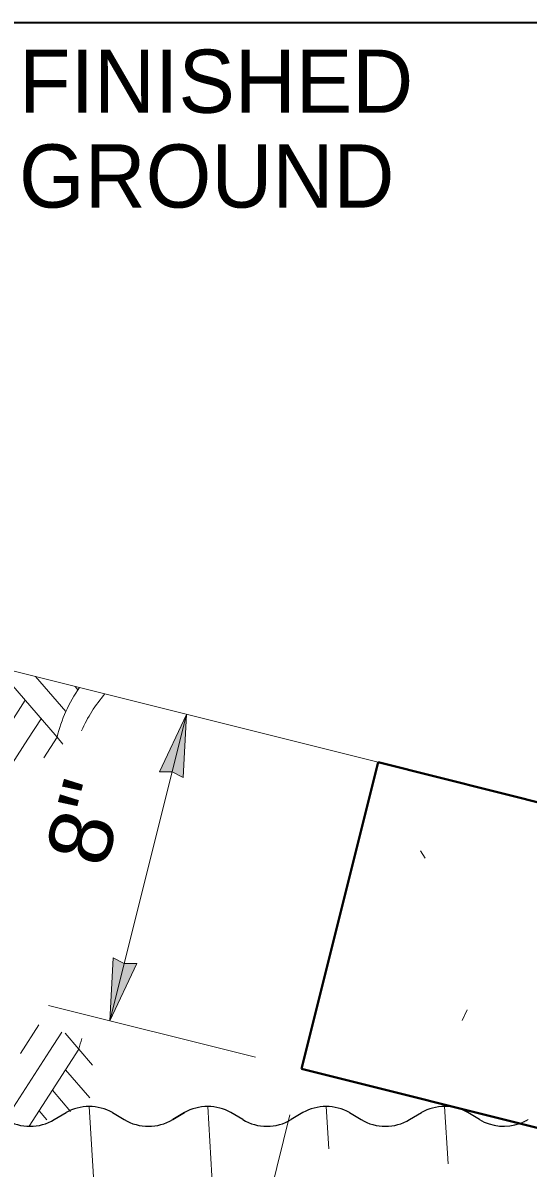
# Model space of a CAD drawing. Extents: x 99860 to 103153, y 99998 to 102077.
# Drawn here: x 100809.3 to 100937.3, y 101785.5 to 102075.5 of the extents above; entities that cross this region are included whole.
import ezdxf
from ezdxf.enums import TextEntityAlignment as Align

# ---------------------------------------------------------------- set-up
doc = ezdxf.new("R2010")
doc.units = 0
doc.header["$LTSCALE"] = 6.4
doc.linetypes.add('MEDIUM_DASHED', pattern=[4.5, 3, -1.5])
for name, color, linetype, lineweight in [('1', 7, 'Continuous', 13), ('13', 7, 'Continuous', 40), ('15', 7, 'Continuous', 13), ('17', 7, 'Continuous', 13), ('20', 7, 'Continuous', 13)]:
    doc.layers.add(name, color=color, linetype=linetype, lineweight=lineweight)

msp = doc.modelspace()

# ---------------------------------------------------------------- hatches: boundary and pattern name
at = {"layer": '15'}
for points in [[(100850.757, 101900.416), (100843.952, 101885.908), (100847.12, 101885.866), (100849.935, 101884.412)], [(100831.354, 101822.804), (100838.16, 101837.312), (100834.992, 101837.353), (100832.176, 101838.808)]]:
    msp.add_hatch(color=256, dxfattribs=at).paths.add_polyline_path(points)

# ---------------------------------------------------------------- linework, layer by layer
at = {"layer": '1'}
for p, q in [((100802.509, 101912.504), (100817.976, 101894.63)), ((100812.53, 101910), (100820.202, 101901.134)), ((100822.552, 101907.496), (100823.266, 101906.67)), ((100803.163, 101893.594), (100809.879, 101903.987)), ((100810.569, 101894.112), (100813.927, 101899.308)), ((100814.619, 101889.435), (100817.976, 101894.63)), ((100817.976, 101894.63), (100819.465, 101892.909)), ((100801.434, 101879.975), (100810.569, 101894.112)), ((100808.687, 101814.591), (100813.329, 101821.775)), ((100816.094, 101815.109), (100819.209, 101819.93)), ((100819.987, 101819.686), (100823.5, 101815.626)), ((100806.958, 101800.971), (100816.094, 101815.109)), ((100810.938, 101796.187), (100823.5, 101815.626)), ((100823.5, 101815.626), (100826.95, 101811.64)), ((100820.142, 101810.43), (100826.294, 101803.321)), ((100816.784, 101805.233), (100821.406, 101799.892)), ((100813.426, 101800.037), (100815.404, 101797.751)), ((100841.12, 101551.125), (100826.12, 101801.125)), ((100871.12, 101551.125), (100856.12, 101801.125)), ((100886.76, 101790.459), (100886.12, 101801.125)), ((100916.992, 101786.6), (100916.12, 101801.125))]:
    msp.add_line(p, q, dxfattribs=at)
at = {"layer": '1', "lineweight": 25}
for p, q in [((100817.259, 101797.811), (100820.246, 101799.589)), ((100831.995, 101799.589), (100834.982, 101797.811)), ((100847.259, 101797.811), (100850.246, 101799.589)), ((100847.259, 101797.811), (100850.246, 101799.589)), ((100850.246, 101799.589), (100847.259, 101797.811)), ((100864.982, 101797.811), (100861.995, 101799.589)), ((100880.246, 101799.589), (100877.259, 101797.811)), ((100891.995, 101799.589), (100894.982, 101797.811)), ((100907.259, 101797.811), (100910.246, 101799.589))]:
    msp.add_line(p, q, dxfattribs=at)
at = {"layer": '1', "lineweight": 35}
msp.add_lwpolyline([(99862, 99999.5), (103151, 99999.5), (103151, 102075.5), (99862, 102075.5)], close=True, dxfattribs=at)
at = {"layer": '1', "lineweight": 25}
for points in [[(100831.995, 101799.589), (100834.982, 101797.811), (100834.983, 101797.813)], [(100847.258, 101797.813), (100847.259, 101797.811), (100850.246, 101799.589)], [(100924.983, 101797.813), (100924.982, 101797.811), (100921.995, 101799.589)]]:
    msp.add_lwpolyline(points, dxfattribs=at)
at = {"layer": '1'}
for centre, start, end in [((100854.493, 101885.766), 145.1795, 166.3566), ((100858.541, 101881.087), 139.25013, 156.14215), ((100860.017, 101806.763), 162.05111, 166.3566)]:
    msp.add_arc(centre, 37.577, start, end, dxfattribs=at)
at = {"layer": '1', "lineweight": 25}
for centre, start, end in [((100826.12, 101789.125), 90, 119.31291), ((100826.12, 101789.125), 60.68709, 90), ((100826.12, 101789.125), 60.68709, 90), ((100856.12, 101789.125), 90, 119.31291), ((100856.12, 101789.125), 90, 119.31291), ((100856.12, 101789.125), 90, 119.31291), ((100856.12, 101789.125), 90, 119.31291), ((100856.12, 101789.125), 60.68709, 90), ((100886.12, 101789.125), 90, 119.31291), ((100886.12, 101789.125), 60.68709, 90), ((100916.12, 101789.125), 90, 119.31291), ((100916.12, 101789.125), 60.68709, 90), ((100811.12, 101808.125), 239.24007, 300.75993), ((100841.12, 101808.125), 239.24007, 300.75993), ((100841.12, 101808.125), 239.24007, 300.75993), ((100841.12, 101808.125), 239.24007, 300.75993), ((100841.12, 101808.125), 239.24007, 300.75993), ((100871.12, 101808.125), 239.24007, 300.75993), ((100901.12, 101808.125), 239.24007, 300.75993), ((100931.12, 101808.125), 239.24007, 289.87391)]:
    msp.add_arc(centre, 12, start, end, dxfattribs=at)
at = {"layer": '1', "linetype": 'MEDIUM_DASHED'}
msp.add_arc((100931.12, 101808.125), 12, 289.92889, 300.75993, dxfattribs=at)
msp.add_arc((100931.12, 101808.125), 12, 289.92889, 300.75993, dxfattribs=at)
at = {"layer": '13'}
for p, q in [((100879.861, 101810.677), (100899.264, 101888.289)), ((100899.264, 101888.289), (102226.12, 101556.572)), ((102146.12, 101494.11), (100879.861, 101810.677))]:
    msp.add_line(p, q, dxfattribs=at)
at = {"layer": '15'}
for p, q in [((100590.476, 101965.486), (100899.264, 101888.289)), ((100831.354, 101822.804), (100850.757, 101900.416)), ((100868.22, 101813.588), (100815.839, 101826.683)), ((100876.951, 101799.036), (100864.547, 101749.42))]:
    msp.add_line(p, q, dxfattribs=at)
for points in [[(100850.757, 101900.416), (100843.952, 101885.908), (100847.12, 101885.866), (100849.935, 101884.412)], [(100831.354, 101822.804), (100838.16, 101837.312), (100834.992, 101837.353), (100832.176, 101838.808)]]:
    msp.add_lwpolyline(points, close=True, dxfattribs=at)
at = {"layer": '17'}
for p, q in [((100910.022, 101865.902), (100911.202, 101864.032)), ((100920.548, 101822.872), (100921.798, 101825.632))]:
    msp.add_line(p, q, dxfattribs=at)

# ---------------------------------------------------------------- texts
at = {"layer": '20'}
for s, p in [('FINISHED', (100808.316, 102052.736)), ('GROUND', (100808.316, 102028.736))]:
    msp.add_text(s, height=16, dxfattribs=at).set_placement(p)
at = {"layer": '20', "width": 1.05}
msp.add_text('8"', height=16, rotation=75.208, dxfattribs=at).set_placement((100832.834, 101871.052), align=Align.CENTER)

doc.saveas('drawing.dxf')
